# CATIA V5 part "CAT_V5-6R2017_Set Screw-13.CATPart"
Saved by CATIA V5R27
Part number: Set Screw-13
Bounding box of the stored display mesh (mm): x -5.916 to 5.916, y -5.992 to 5.992, z -1.5 to 16
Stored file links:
  E:\_Deepak\2017_Deepak\CATIA\Resources\Tutorial Files\Tutorials\c16_catia_v5_6r2016_tut\Bench vice\CAT_V5-6R2016_Set Screw-13.CATPart
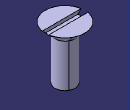
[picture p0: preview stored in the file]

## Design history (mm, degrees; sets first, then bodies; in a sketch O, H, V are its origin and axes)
Body1 (main body)
  Sketch1 on yz-plane, origin (0, 0, 0), H (0, 1, 0), V (0, 0, 1)
    point P1 (0, -1.5)
    line L1 (0, -1.5) -> (3, 0)
    point P2 (3, 0)
    line L2 (3, 0) -> (3, 13)
    line L3 (3, 13) -> (6, 16)
    point P4 (6, 16)
    line L4 (6, 16) -> (0, 16)
    point P5 (0, 16)
    line L5 (0, 16) -> (0, -1.5)
    length L2 = 13
    distance L2 L5 = 3
    distance H P1 = 1.5
    distance P4 L5 = 6
    angle L3 L5 = 45
    coincidence: P1 V, P2 H, P5 V
    vertical: L2 V, L5 V
    horizontal: L4 H
  Shaft1: profile Sketch1, axis edge of Sketch1, angle 360
  Sketch2 on yz-plane, origin (0, 0, 0), H (0, 1, 0), V (0, 0, 1)
    line L1 (-1, 16) -> (1, 16)
    line L2 (1, 16) -> (1, 15)
    line L3 (1, 15) -> (-1, 15)
    line L4 (-1, 15) -> (-1, 16)
    reference projected line E1 (-6, 16) -> (6, 16) from edge of Shaft1
    distance V L2 = 1
    length L1 = 2
    length L2 = 1
    horizontal: L1 H, L3 H
    vertical: L2 V, L4 V
    coincidence: L1 E1
  Pocket1: profile Sketch2, direction (-1, 0, 0), length 16, mirrored extent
